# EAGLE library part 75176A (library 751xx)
DIFFERENTIAL BUS TRANSCEIVER Source: http://focus.ti.com/lit/ds/symlink/sn75176a.pdf
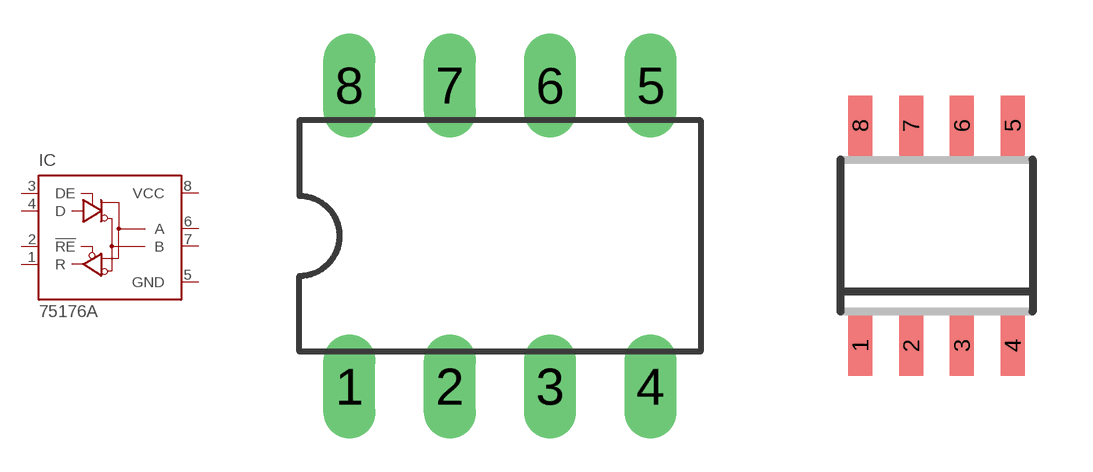
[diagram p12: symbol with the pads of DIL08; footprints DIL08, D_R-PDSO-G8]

Designator prefix IC

## 75176AP  [DIL08]
1  R  in
2  !RE  in
3  DE  in
4  D  in
5  GND  pwr
6  A  out
7  B  out
8  VCC  pwr

## 75176AD  [D_R-PDSO-G8]
Pads as for DIL08

## Footprint DIL08 (pad centres in mm)
Dual In Line Package
drill 0.813 long: 1 -3.81,-3.81; 2 -1.27,-3.81; 3 1.27,-3.81; 4 3.81,-3.81; 5 3.81,3.81; 6 1.27,3.81; 7 -1.27,3.81; 8 -3.81,3.81

## Footprint D_R-PDSO-G8 (pad centres in mm)
D (R-PDSO-G8) Source: http://focus.ti.com/lit/ds/slos063b/slos063b.pdf
smd 0.6 x 1.5: 1 -1.905,-2.75; 2 -0.635,-2.75; 3 0.635,-2.75; 4 1.905,-2.75; 5 1.905,2.75; 6 0.635,2.75; 7 -0.635,2.75; 8 -1.905,2.75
